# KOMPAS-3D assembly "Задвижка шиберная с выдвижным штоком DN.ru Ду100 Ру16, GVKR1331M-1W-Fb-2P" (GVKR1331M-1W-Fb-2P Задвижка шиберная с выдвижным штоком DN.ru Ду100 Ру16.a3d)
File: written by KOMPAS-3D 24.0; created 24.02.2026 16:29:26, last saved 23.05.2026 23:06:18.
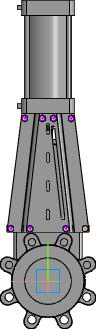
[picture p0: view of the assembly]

Document properties: Автор: R2D2; Полное имя файла: E:\Работа\Зайцев\GVKR1331M-1W-Fb-2P Задвижка шиберная с выдвижным штоком DN.ru Ду50-300 Ру16-10-6 с пневмоприводом\исходные материалы\DN100\GVKR1331M-1W-Fb-2P Задвижка шиберная с выдвижным штоком DN.ru Ду100 Ру16.a3d

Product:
- Component [detail]: Затвор дисковый DN.ru Ду Ру  | qty 1  | pos. 1  | Масса: 18.2; Раздел спецификации: Прочие изделия; Примечание: D050-23732; Автор: R2D2; source file: Задвижка шиберная РЕЗЬБОВОЙ DN.ru Ду Ру.m3d
- Component [detail]: Пневмоцилиндр  | qty 1  | pos. 2  | Масса: 19.177764; Автор: R2D2; source file: Пневмоцилиндр.m3d
- Component [standard]: Hexagon head screw ISO 4017 - М8 x 16  | qty 16  | Масса: 0.012085; Раздел спецификации: Стандартные изделия; Рассекать на разрезах: no
- Component [detail]: лист  | qty 2  | pos. 3  | Масса: 1.297865; Раздел спецификации: Прочие изделия; Примечание: D040-08800; Автор: R2D2; source file: лист.m3d
- Component [detail]: шибер  | qty 1  | pos. 4  | Масса: 1.371403; Раздел спецификации: Прочие изделия; Примечание: D040-08800; Автор: R2D2; source file: шибер.m3d
- Part/product: Задвижка шиберная с выдвижным штоком DN.ru Ду100 Ру16  | designation GVKR1331M-1W-Fb-2P
    Масса: 12.5
    Раздел спецификации: Прочие изделия
    Примечание: D040-08794

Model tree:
1. Точка:1  (with: Ребро.Отверстие в листовом теле:2)
     X = -38.5532; Y = 112.5; Z = 46
2. Точка:2  (with: Ребро.Отверстие в листовом теле:3)
     X = 38.5532; Y = 112.5; Z = 46
3. Точка:3  (with: Ребро.Отверстие в листовом теле:4)
     X = 79.4958; Y = 112.5; Z = 27.5
4. Точка:4  (with: Ребро.Отверстие в листовом теле:5)
     X = -49.7006; Y = 349; Z = 27.5
5. Точка:5  (with: Ребро.Отверстие в листовом теле:6)
     X = -12.0427; Y = 349; Z = 46
6. Точка:6  (with: Ребро.Отверстие в листовом теле:7)
     X = 12.0427; Y = 349; Z = 46
7. Точка:7  (with: Ребро.Отверстие в листовом теле:8)
     X = 49.7006; Y = 349; Z = 27.5
8. Массив по точкам:1
9. Экземпляр ( 6 )
10. Экземпляр ( 4 )
11. Экземпляр ( 1 )
12. Экземпляр ( 7 )
13. Экземпляр ( 3 )
14. Экземпляр ( 5 )
15. Экземпляр ( 2 )
16. Контекстная связь:1  (with: Эскиз:7, Грань.Элемент выдавливания:6, Ребро.Элемент выдавливания:6, Ребро.Элемент выдавливания:12, Контекстная связь (лист (1)):1)
17. Контекстная связь:2  (with: Эскиз:6, Грань.Элемент выдавливания:15, Ребро.Элемент выдавливания:15, Контекстная связь (лист (1)):2)
18. Контекстная связь:3  (with: Эскиз:5, Грань.Элемент выдавливания:1, Вершина.Элемент выдавливания:15, Контекстная связь (шибер):3, Грань.Элемент выдавливания:8, Грань.Отверстие в листовом теле:1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)
     Ориентация = 2; Ориентация = 2; Ориентация = 2; Ориентация = 2; Ориентация = 2; Ориентация = 2; Ориентация = 2; Ориентация = 2; Ориентация = 2

Expressions: D050-23732; D040-08800
Referenced files in E:\Работа\Зайцев\GVKR1331M-1W-Fb-2P Задвижка шиберная с выдвижным штоком DN.ru Ду50-300 Ру16-10-6 с пневмоприводом\исходные материалы\DN100\: Задвижка шиберная РЕЗЬБОВОЙ DN.ru Ду Ру.m3d, Пневмоцилиндр.m3d, лист.m3d, шибер.m3d
Referenced files in C:\Program Files\ASCON\KOMPAS-3D v24\Libs\PolynomLib\DATA\vault\Methods\Kompas\3D\: PLib_Bolt_1_ISO_1100.m3d
Referenced files in E:\Работа\Зайцев\GVKR1331E-1W-Fb-2P Задвижка шиберная DN.ru Ду50-300 Ру16-10-6\исходные материалы\DN80\: лист.m3d
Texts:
  Hexagon head screw
  BOSimple***PART:17775d1c-e7de-f283-40f0-d40789f7f59e***SHORTLOC:A259_7B16EF33AB1642D2[13;1,25;16;8;-;Undefined]
  Программные изделия  и базы данных
  GVKR1331M-1W-Fb-2P
  Hexagon head screw ISO 4017 - М8 x 16 (1)
  hole1
  hole2
  лист (1)
  лист (2)
  Hexagon head screw ISO 4017 - М8 x 16 (9)
  Hexagon head screw ISO 4017 - М8 x 16 (10)
  Hexagon head screw ISO 4017 - М8 x 16 (11)
  Hexagon head screw ISO 4017 - М8 x 16 (12)
  Hexagon head screw ISO 4017 - М8 x 16 (13)
  Hexagon head screw ISO 4017 - М8 x 16 (14)
  Hexagon head screw ISO 4017 - М8 x 16 (15)
  Hexagon head screw ISO 4017 - М8 x 16 (16)
  Ось Y.Начало координат
  Плоскость ZY.Начало координат
  Плоскость ZX.Начало координат
  Плоскость XY.Начало координат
